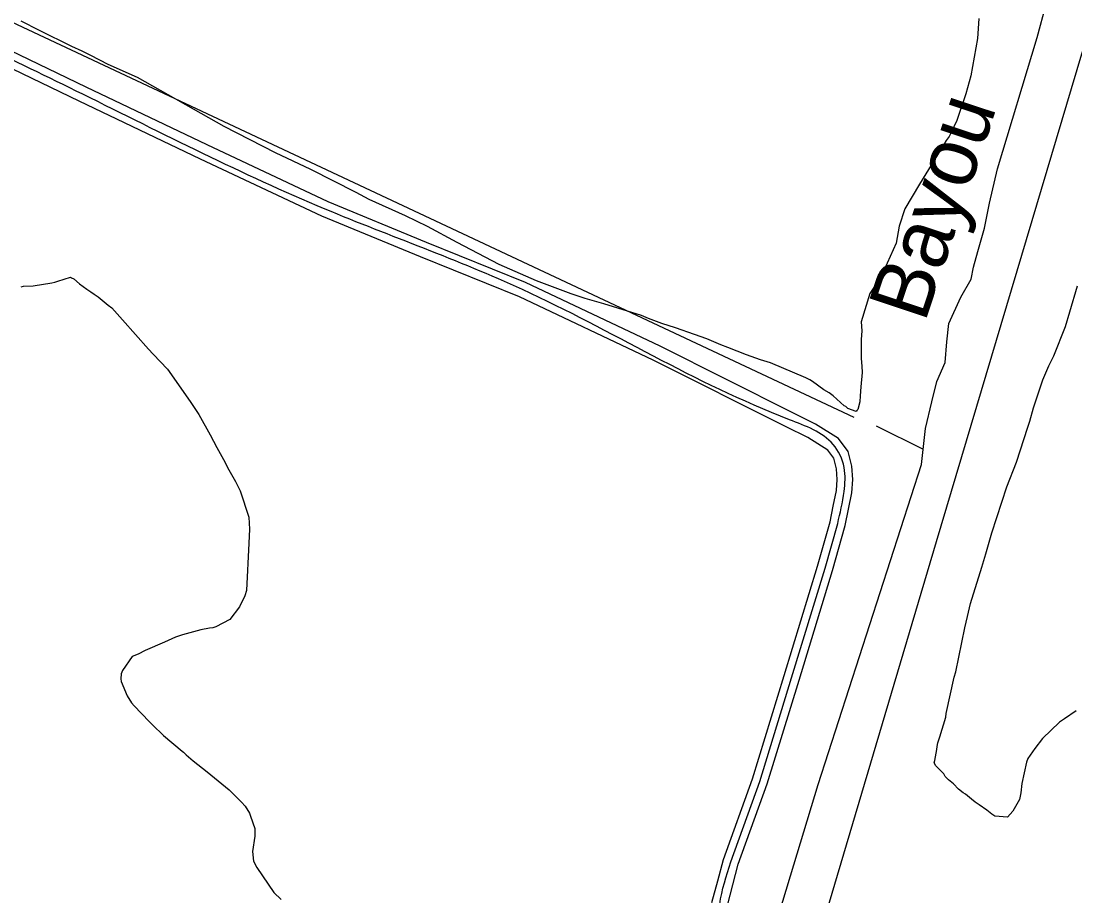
# Model space of a CAD drawing. Extents: x 3683613 to 3738215, y 469626 to 495384.
# Drawn here: x 3688941 to 3690972, y 482951 to 484637 of the extents above; entities that cross this region are included whole.
import ezdxf

# ---------------------------------------------------------------- set-up
doc = ezdxf.new("R2010")
doc.units = 0
for name, color, linetype in [('V-RIVR-IDEN', 7, 'Continuous'), ('V-ROAD-CNTR', 7, 'Continuous'), ('V-SITE-VEGE', 7, 'Continuous'), ('V-TOPO-SHOR', 7, 'Continuous')]:
    doc.layers.add(name, color=color, linetype=linetype)

msp = doc.modelspace()

# ---------------------------------------------------------------- linework, layer by layer
at = {"layer": 'V-ROAD-CNTR'}
for points in [[(3689722.3, 484210), (3689532.7, 484288.3), (3689299.3, 484398.1), (3689066.2, 484509.4), (3688864.5, 484606.6), (3688662.8, 484703.8), (3687739.2, 485140.1)], [(3689710.9, 484182.2), (3689520.6, 484260.9), (3689286.5, 484371), (3689053.2, 484482.4), (3688851.5, 484579.6), (3688649.9, 484676.7), (3687739.5, 485106.8)], [(3690302.1, 482932.3), (3690312.5, 482971.8), (3690323.1, 483011.7), (3690379, 483166.7), (3690440.2, 483366.8), (3690504.9, 483577.9), (3690529.4, 483664.7), (3690535.7, 483696.2), (3690542, 483727.9), (3690544.1, 483753.1), (3690542, 483779), (3690534.7, 483807.5), (3690516.3, 483832.1), (3690472, 483860.1), (3690428.6, 483881.9), (3690172.4, 484010.2), (3689913.4, 484133.1), (3689722.2, 484210)], [(3690272.5, 482937.8), (3690283.5, 482979.4), (3690294.4, 483020.6), (3690350.5, 483176.2), (3690411.5, 483375.6), (3690476.1, 483586.3), (3690500.2, 483671.8), (3690506.2, 483702), (3690512.2, 483732.1), (3690514, 483753.2), (3690512.3, 483774), (3690507.1, 483794.3), (3690495.6, 483809.7), (3690457.2, 483834), (3690415.2, 483855.1), (3690159.3, 483983.2), (3689901.4, 484105.6), (3689711, 484182.2)], [(3690308.7, 483016.1), (3690364.8, 483171.4), (3690425.9, 483371.2), (3690490.5, 483582.1), (3690514.8, 483668.3)]]:
    msp.add_lwpolyline(points, dxfattribs=at)
for points in [[(3690514.8, 483668.3), (3690527.1, 483730), (3690527.2, 483776.5), (3690505.9, 483820.9), (3690421.9, 483868.5), (3689907.4, 484119.4), (3689526.7, 484274.6), (3689059.7, 484495.9), (3688656.3, 484690.3)], [(3690345, 482790.1), (3690301.6, 482816.1), (3690285.4, 482868.9), (3690287.3, 482935), (3690308.7, 483016.1)]]:
    msp.add_spline(points, degree=3, dxfattribs=at)
at = {"layer": 'V-SITE-VEGE'}
for p, q in [((3690786.8, 484642), (3690783.9, 484603.6)), ((3688976.5, 484618.6), (3688941, 484636.9)), ((3689038.9, 484587.8), (3688976.5, 484618.6)), ((3690783.9, 484603.6), (3690771.3, 484531.5)), ((3689059, 484579.2), (3689038.9, 484587.8)), ((3689075.3, 484570.5), (3689059, 484579.2)), ((3689108.9, 484553.1), (3689075.3, 484570.5)), ((3689165.5, 484528.1), (3689108.9, 484553.1)), ((3689332.5, 484433.7), (3689165.5, 484528.1)), ((3690771.3, 484531.5), (3690761.6, 484497)), ((3690761.6, 484497), (3690744.3, 484445.2)), ((3690744.3, 484445.2), (3690733.7, 484422.1)), ((3689431.4, 484382.7), (3689332.5, 484433.7)), ((3690733.7, 484422.1), (3690729.8, 484414.4)), ((3690719.2, 484399.1), (3690672.1, 484322.3)), ((3690724.1, 484406.8), (3690719.2, 484399.1)), ((3690729.8, 484414.4), (3690724.1, 484406.8)), ((3689499.5, 484350.9), (3689431.4, 484382.7)), ((3689586.8, 484306.6), (3689499.5, 484350.9)), ((3690672.1, 484322.3), (3690644.2, 484275.3)), ((3689611.8, 484293.1), (3689586.8, 484306.6)), ((3689681.8, 484261.3), (3689611.8, 484293.1)), ((3690644.2, 484275.3), (3690633.5, 484241.7)), ((3689724.1, 484241.1), (3689681.8, 484261.3)), ((3689781.6, 484210.3), (3689724.1, 484241.1)), ((3690633.5, 484241.7), (3690627.7, 484209.1)), ((3689862.3, 484167.9), (3689781.6, 484210.3)), ((3690627.7, 484209.1), (3690598.8, 484144.8)), ((3689893, 484154.4), (3689862.3, 484167.9)), ((3689934.2, 484136.1), (3689893, 484154.4)), ((3688964, 484126.8), (3689000.5, 484132.5)), ((3689000.5, 484132.5), (3689006.2, 484133.4)), ((3689006.2, 484133.4), (3689012, 484135.3)), ((3689012, 484135.3), (3689036, 484143)), ((3689036, 484143), (3689037.9, 484142)), ((3689037.9, 484142), (3689042.7, 484140.1)), ((3689042.7, 484140.1), (3689053.3, 484130.5)), ((3689053.3, 484130.5), (3689067.7, 484119.9)), ((3690001.4, 484111.1), (3689934.2, 484136.1)), ((3690591.1, 484133.3), (3690576.7, 484112.1)), ((3690598.8, 484144.8), (3690591.1, 484133.3)), ((3688940.9, 484124.9), (3688945.7, 484125.8)), ((3688945.7, 484125.8), (3688964, 484126.8)), ((3689067.7, 484119.9), (3689075.4, 484115.1)), ((3689075.4, 484115.1), (3689082.1, 484110.3)), ((3689082.1, 484110.3), (3689089.7, 484105.5)), ((3690028.3, 484102.4), (3690001.4, 484111.1)), ((3690576.7, 484112.1), (3690560.3, 484057.4)), ((3689089.7, 484105.5), (3689108.9, 484089.1)), ((3690063.8, 484091.8), (3690028.3, 484102.4)), ((3690136.8, 484069.6), (3690063.8, 484091.8)), ((3689108.9, 484089.1), (3689115.6, 484084.3)), ((3689115.6, 484084.3), (3689136.7, 484061.2)), ((3690150.2, 484063.8), (3690136.8, 484069.6)), ((3689136.7, 484061.2), (3689186.6, 484004.5)), ((3690176.1, 484054.1), (3690150.2, 484063.8)), ((3690202.1, 484045.5), (3690176.1, 484054.1)), ((3690560.3, 484057.4), (3690561.2, 484040.1)), ((3690238.5, 484032.9), (3690202.1, 484045.5)), ((3690262.5, 484024.2), (3690238.5, 484032.9)), ((3690561.2, 484040.1), (3690560.2, 484022.9)), ((3690289.4, 484012.7), (3690262.5, 484024.2)), ((3690302.8, 484007.9), (3690289.4, 484012.7)), ((3690560.2, 484022.9), (3690560.2, 483986.4)), ((3689186.6, 484004.5), (3689195.2, 483994.9)), ((3689195.2, 483994.9), (3689223, 483966)), ((3690339.3, 483993.4), (3690302.8, 484007.9)), ((3690366.2, 483983.8), (3690339.3, 483993.4)), ((3690385.4, 483978), (3690366.2, 483983.8)), ((3690453.5, 483949.1), (3690385.4, 483978)), ((3690560.2, 483986.4), (3690561.1, 483972)), ((3690561.1, 483972), (3690562.1, 483959.5)), ((3689223, 483966), (3689267.1, 483903.5)), ((3690461.2, 483945.2), (3690453.5, 483949.1)), ((3690562.1, 483959.5), (3690559.1, 483931.6)), ((3690466, 483942.3), (3690461.2, 483945.2)), ((3690488.1, 483926), (3690466, 483942.3)), ((3690559.1, 483931.6), (3690558.2, 483914.3)), ((3690498.6, 483920.2), (3690488.1, 483926)), ((3690506.3, 483914.4), (3690498.6, 483920.2)), ((3690527.4, 483895.2), (3690506.3, 483914.4)), ((3690558.2, 483914.3), (3690557.2, 483902.8)), ((3689267.1, 483903.5), (3689283.4, 483878.5)), ((3690530.3, 483894.2), (3690527.4, 483895.2)), ((3690534.1, 483890.4), (3690530.3, 483894.2)), ((3690550.4, 483884.6), (3690534.1, 483890.4)), ((3690553.3, 483888.4), (3690551.4, 483886.5)), ((3690557.2, 483902.8), (3690553.3, 483888.4)), ((3689283.4, 483878.5), (3689305.4, 483839.1)), ((3690551.4, 483886.5), (3690550.4, 483884.6)), ((3689305.4, 483839.1), (3689317.9, 483815.1)), ((3689317.9, 483815.1), (3689334.2, 483786.3)), ((3689334.2, 483786.3), (3689339, 483776.6)), ((3689339, 483776.6), (3689354.3, 483749.7)), ((3689354.3, 483749.7), (3689362.9, 483731.5)), ((3689362.9, 483731.5), (3689380.1, 483680.6)), ((3689380.1, 483680.6), (3689381.1, 483657.5)), ((3689381.1, 483657.5), (3689380.1, 483630.6)), ((3689380.1, 483630.6), (3689375.1, 483539.4)), ((3689372.2, 483528.8), (3689361.6, 483507.7)), ((3689375.1, 483539.4), (3689372.2, 483528.8)), ((3689361.6, 483507.7), (3689343.3, 483483.7)), ((3689343.3, 483483.7), (3689316.4, 483469.4)), ((3689287.6, 483463.6), (3689252.1, 483454.1)), ((3689303.9, 483466.5), (3689287.6, 483463.6)), ((3689310.7, 483467.4), (3689303.9, 483466.5)), ((3689316.4, 483469.4), (3689310.7, 483467.4)), ((3689238.6, 483449.3), (3689217.5, 483439.7)), ((3689252.1, 483454.1), (3689238.6, 483449.3)), ((3689180, 483423.5), (3689166.5, 483416.8)), ((3689217.5, 483439.7), (3689180, 483423.5)), ((3689155, 483412), (3689136.7, 483385.1)), ((3689166.5, 483416.8), (3689155, 483412)), ((3689136.7, 483385.1), (3689133.8, 483378.4)), ((3689133.8, 483378.4), (3689132.9, 483368.8)), ((3689132.9, 483368.8), (3689133.8, 483364)), ((3689133.8, 483364), (3689145.3, 483336.1)), ((3689145.3, 483336.1), (3689153.9, 483322.7)), ((3689153.9, 483322.7), (3689158.7, 483316.9)), ((3689158.7, 483316.9), (3689187.5, 483287.1)), ((3689187.5, 483287.1), (3689194.2, 483280.3)), ((3689194.2, 483280.3), (3689215.3, 483260.1)), ((3689215.3, 483260.1), (3689251.7, 483229.4)), ((3689251.7, 483229.4), (3689253.7, 483227.4)), ((3689253.7, 483227.4), (3689259.4, 483222.6)), ((3689259.4, 483222.6), (3689272.8, 483211.1)), ((3689272.8, 483211.1), (3689299.7, 483189.9)), ((3689299.7, 483189.9), (3689335.2, 483161.1)), ((3689335.2, 483161.1), (3689341.9, 483155.3)), ((3689341.9, 483155.3), (3689365.9, 483131.2)), ((3689365.9, 483131.2), (3689372.6, 483123.5)), ((3689372.6, 483123.5), (3689381.2, 483110.1)), ((3689381.2, 483110.1), (3689383.1, 483104.3)), ((3689383.1, 483104.3), (3689391.7, 483080.3)), ((3689391.7, 483080.3), (3689391.7, 483065.9)), ((3689391.7, 483065.9), (3689386.9, 483036.1)), ((3689386.9, 483036.1), (3689388.8, 483017.9)), ((3689388.8, 483017.9), (3689395.5, 483005.4)), ((3689395.5, 483005.4), (3689428.1, 482957.3)), ((3689428.1, 482957.3), (3689442.4, 482943.9))]:
    msp.add_line(p, q, dxfattribs=at)
for points in [[(3690761.2, 483146.5), (3690756.4, 483149.4), (3690747.8, 483156.1), (3690738.2, 483166.7), (3690728.6, 483174.4), (3690721.9, 483181.1), (3690719, 483185.9), (3690703.7, 483201.3), (3690700.8, 483207.1), (3690701.8, 483211.9), (3690705.6, 483233), (3690706.6, 483238.8), (3690707.6, 483245.5), (3690711.4, 483257), (3690723, 483295.4), (3690724, 483302.1), (3690739.4, 483372.2), (3690742.3, 483382.8), (3690759.7, 483467.2), (3690764.6, 483489.3), (3690770.4, 483514.3), (3690792.6, 483584.4), (3690800.3, 483610.3), (3690811.9, 483650.6), (3690840.8, 483738.9), (3690859.1, 483786.9), (3690881.3, 483854.1), (3690885.2, 483865.6), (3690891.9, 483891.5), (3690910.3, 483945.3), (3690921.8, 483972.2), (3690931.4, 483991.4), (3690953.6, 484048), (3690962.3, 484076.8), (3690976.8, 484126.7)], [(3690974.6, 483307.5), (3690951.6, 483292.2), (3690942, 483285.5), (3690909.3, 483253.8), (3690894.8, 483234.6), (3690881.4, 483215.5), (3690878.5, 483208.7), (3690869.8, 483167.5), (3690867.8, 483149.2), (3690864.9, 483136.7), (3690852.4, 483113.7), (3690841.8, 483102.2), (3690817.8, 483104.1), (3690812.1, 483108), (3690802.5, 483115.7), (3690787.1, 483126.3), (3690779.4, 483131.1), (3690772.7, 483136.9), (3690761.2, 483146.5)]]:
    msp.add_lwpolyline(points, dxfattribs=at)
at = {"layer": 'V-TOPO-SHOR'}
msp.add_line((3690589.1, 483856.5), (3690679.4, 483811.8), dxfattribs=at)
for points in [[(3687741.6, 485194), (3688681.1, 484749.3), (3690546.1, 483873.3)], [(3689853.7, 481124.9), (3689918, 481328.5), (3690219.6, 482314.7), (3690477, 483165.6), (3690676.2, 483782.5), (3690683.7, 483851.7), (3690696.4, 483903.1), (3690705.9, 483942), (3690721.6, 483978.7), (3690724.9, 484018.5), (3690729.1, 484054.2), (3690752.3, 484104.6), (3690772.3, 484139.2), (3690776.5, 484162.3), (3690784.9, 484192.7), (3690797.6, 484237.8), (3690807.1, 484286.1), (3690823, 484352.2), (3690898.9, 484605), (3691003.1, 484991.2)], [(3690993.1, 484598.7), (3690984.9, 484573.4), (3690704.4, 483633.4), (3690456.5, 482797.2), (3690184.4, 481930.6), (3689782.6, 480608.6), (3689342.8, 479148.1), (3689319.7, 479071.6)]]:
    msp.add_lwpolyline(points, dxfattribs=at)

# ---------------------------------------------------------------- texts
at = {"layer": 'V-RIVR-IDEN'}
msp.add_text('Bayou', height=116, rotation=71.5651, dxfattribs=at).set_placement((3690682.4, 484053.7))

doc.saveas('drawing.dxf')
